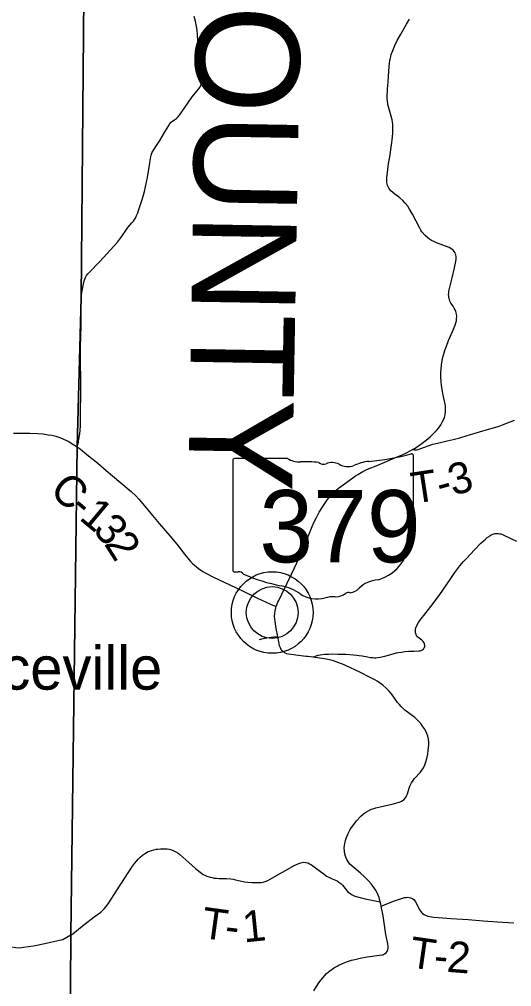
# Model space of a CAD drawing. Extents: x 0 to 34, y 0 to 22.
# Drawn here: x 7.038 to 7.936, y 15.399 to 17.164 of the extents above; entities that cross this region are included whole.
import ezdxf

# ---------------------------------------------------------------- set-up
doc = ezdxf.new("R2010")
doc.units = 0
for name, color, linetype in [('GM_X_Corporation', 7, 'Continuous'), ('GM_X_County_Road', 7, 'Continuous'), ('GM_X_County_Road_Text', 7, 'Continuous'), ('GM_X_County_Text', 7, 'Continuous'), ('GM_X_State_Location', 7, 'Continuous'), ('GM_X_State_Route', 7, 'Continuous'), ('GM_X_State_Shield', 7, 'Continuous'), ('GM_X_Township_Road', 7, 'Continuous'), ('GM_X_Township_Road_Text', 7, 'Continuous'), ('GM_X_Township_Text', 7, 'Continuous'), ('GM_X_Unincorporated', 7, 'Continuous'), ('GM_X_Unincorporated_Location', 7, 'Continuous'), ('GM_X_Unincorporated_Text', 7, 'Continuous')]:
    doc.layers.add(name, color=color, linetype=linetype)

msp = doc.modelspace()

# ---------------------------------------------------------------- linework, layer by layer
at = {"layer": 'GM_X_Corporation'}
msp.add_lwpolyline([(7.1227, 14.1), (8.9, 14.1), (8.9, 20.9), (7.231, 20.9), (7.2244, 20.2649), (7.1982, 19.2496), (7.1981, 19.2461), (7.1974, 19.2018), (7.1957, 19.0991), (7.1992, 18.9556), (7.197, 18.9465), (7.1949, 18.8464), (7.1846, 18.5133), (7.1817, 18.3306), (7.1804, 18.2238), (7.1572, 17.4131), (7.1504, 16.6562), (7.1434, 16.3848), (7.1318, 15.4937)], close=True, dxfattribs=at)
at = {"layer": 'GM_X_County_Road'}
for points in [[(7.0275, 16.409), (7.0571, 16.4092), (7.0714, 16.4087), (7.0815, 16.4078), (7.0903, 16.4063), (7.0974, 16.4054), (7.1045, 16.4037), (7.1116, 16.4013), (7.1184, 16.3986), (7.127, 16.3944), (7.1356, 16.3895), (7.1436, 16.3842)], [(7.1436, 16.3842), (7.1497, 16.3798), (7.161, 16.3705), (7.1808, 16.3543), (7.196, 16.3409), (7.2232, 16.3184), (7.2418, 16.3028), (7.2505, 16.2949), (7.2559, 16.2891), (7.2603, 16.284), (7.281, 16.2592), (7.293, 16.2445), (7.3126, 16.2219), (7.3252, 16.2067), (7.3296, 16.2011), (7.3373, 16.191)], [(7.3373, 16.191), (7.3387, 16.1891), (7.345, 16.1812), (7.3503, 16.175), (7.3537, 16.1714), (7.3607, 16.1653), (7.3645, 16.1623), (7.3691, 16.1592), (7.3728, 16.1569), (7.377, 16.1545), (7.3922, 16.1465), (7.4215, 16.1325), (7.4459, 16.1209), (7.4719, 16.1082), (7.4957, 16.0973), (7.5062, 16.093)]]:
    msp.add_lwpolyline(points, dxfattribs=at)
at = {"layer": 'GM_X_State_Route'}
msp.add_line((7.5737, 16.0006), (7.5639, 16.0017), dxfattribs=at)
for points in [[(7.755, 16.3792), (7.7595, 16.3818), (7.7641, 16.3849), (7.7698, 16.3891), (7.7825, 16.399), (7.7874, 16.4033), (7.7958, 16.411), (7.7985, 16.4139), (7.8026, 16.4189), (7.8041, 16.4209), (7.8067, 16.4247), (7.809, 16.4291), (7.8111, 16.4334), (7.8129, 16.4378), (7.8142, 16.4429), (7.8148, 16.448), (7.8151, 16.4526), (7.8148, 16.4587), (7.8143, 16.4627), (7.8134, 16.4677), (7.8104, 16.4814), (7.8088, 16.4893), (7.8077, 16.4965), (7.8069, 16.5033), (7.8066, 16.5113), (7.8067, 16.5204), (7.807, 16.5263), (7.8078, 16.5338), (7.809, 16.5418), (7.8103, 16.548), (7.812, 16.5543), (7.8143, 16.5619), (7.8165, 16.5681), (7.8207, 16.5785), (7.8278, 16.595), (7.8327, 16.6066), (7.834, 16.6107), (7.8348, 16.6141), (7.8353, 16.6177), (7.8356, 16.6228), (7.8351, 16.6265), (7.8346, 16.6288), (7.8336, 16.6315), (7.8324, 16.6343), (7.8309, 16.6371), (7.8287, 16.6409), (7.825, 16.6464), (7.823, 16.6504), (7.822, 16.6535), (7.8213, 16.6563), (7.8208, 16.6591), (7.8207, 16.6621), (7.8208, 16.665), (7.8212, 16.6681), (7.8226, 16.6756), (7.8269, 16.693), (7.8313, 16.7111), (7.834, 16.7227), (7.8347, 16.7267), (7.8345, 16.7311), (7.8338, 16.7346), (7.8333, 16.7361), (7.8324, 16.7383), (7.831, 16.7409), (7.8287, 16.7435), (7.8248, 16.7464), (7.8216, 16.7481), (7.7983, 16.7567), (7.7936, 16.7588), (7.7896, 16.7609), (7.7859, 16.7633), (7.7827, 16.7656), (7.7776, 16.77), (7.7721, 16.7769), (7.77, 16.7799), (7.7679, 16.7833), (7.7548, 16.8089), (7.7496, 16.8182), (7.746, 16.8234), (7.7415, 16.8289), (7.7371, 16.8336), (7.7318, 16.8384), (7.7229, 16.8454), (7.7155, 16.8515), (7.7134, 16.8541), (7.7119, 16.8563), (7.7106, 16.8588), (7.7095, 16.8614), (7.7086, 16.8641), (7.7081, 16.8668), (7.7078, 16.8696), (7.708, 16.8752), (7.7098, 16.8905), (7.7112, 16.9013), (7.7132, 16.9136), (7.7173, 16.9395), (7.718, 16.9445), (7.7189, 16.9558), (7.7191, 16.9629), (7.7188, 16.9729), (7.7182, 16.9775), (7.7176, 16.981), (7.7161, 16.988), (7.7111, 17.005), (7.7101, 17.0088), (7.7096, 17.0115), (7.709, 17.0147), (7.7085, 17.0209), (7.7094, 17.0377), (7.7102, 17.0495), (7.7115, 17.0696), (7.7129, 17.0851), (7.7134, 17.0884), (7.714, 17.0916), (7.7152, 17.0967), (7.7162, 17.1004), (7.7187, 17.1078), (7.7224, 17.1168), (7.7266, 17.1255), (7.7333, 17.1375), (7.7436, 17.1553), (7.7493, 17.165)], [(7.6913, 16.3511), (7.7271, 16.3661), (7.7347, 16.3693), (7.7437, 16.3734), (7.7505, 16.3768), (7.755, 16.3792)], [(7.5062, 16.093), (7.5095, 16.1007), (7.511, 16.1039), (7.5164, 16.1153), (7.5347, 16.1532), (7.5486, 16.1828), (7.5521, 16.1907), (7.5576, 16.2038), (7.5705, 16.2358), (7.5718, 16.2389), (7.575, 16.246), (7.5789, 16.254), (7.5849, 16.2649), (7.5914, 16.2754), (7.596, 16.2826), (7.5999, 16.2883), (7.6021, 16.2912), (7.6053, 16.295), (7.6115, 16.3018), (7.6156, 16.3054), (7.6196, 16.3087), (7.637, 16.3213), (7.6509, 16.3313), (7.6553, 16.3341), (7.6641, 16.3392), (7.6729, 16.3433), (7.6913, 16.3511)], [(7.5639, 16.0017), (7.561, 16.002), (7.5422, 16.0041), (7.5287, 16.0062), (7.5258, 16.0069), (7.5229, 16.008), (7.5212, 16.0091), (7.518, 16.0115), (7.5155, 16.0147), (7.5141, 16.0173), (7.5126, 16.0215), (7.5111, 16.0284), (7.5092, 16.0384), (7.5065, 16.0531), (7.5045, 16.0656), (7.5038, 16.0705), (7.5035, 16.0756), (7.5037, 16.0804), (7.5043, 16.0852), (7.5055, 16.0904), (7.5062, 16.093)], [(7.5751, 15.392), (7.5828, 15.4043), (7.5858, 15.4086), (7.5911, 15.4153), (7.5983, 15.4232), (7.604, 15.428), (7.6083, 15.4312), (7.6126, 15.4341), (7.6174, 15.4369), (7.6213, 15.439), (7.6248, 15.4406), (7.6315, 15.4433), (7.6382, 15.4457), (7.6435, 15.4474), (7.6496, 15.4491), (7.6592, 15.4513), (7.6724, 15.4535), (7.6987, 15.4571), (7.7, 15.4574), (7.7022, 15.4582), (7.7037, 15.4591), (7.7065, 15.4612), (7.7084, 15.4636), (7.7097, 15.4669), (7.7103, 15.4696), (7.7104, 15.4727), (7.7096, 15.4773), (7.7061, 15.4947), (7.7036, 15.5114), (7.7014, 15.5285), (7.6978, 15.5463), (7.697, 15.5499), (7.6961, 15.5539), (7.694, 15.5619), (7.6922, 15.5663), (7.6903, 15.5704), (7.6883, 15.5741), (7.686, 15.578), (7.6833, 15.5821), (7.6797, 15.5868), (7.6747, 15.5925), (7.6674, 15.5995), (7.6599, 15.6064), (7.6408, 15.623), (7.6368, 15.6281), (7.6348, 15.6315), (7.6331, 15.6355), (7.6324, 15.6376), (7.6315, 15.641), (7.6307, 15.6463), (7.6305, 15.6519), (7.6309, 15.6573), (7.6313, 15.6597), (7.6318, 15.6627), (7.6334, 15.6687), (7.6354, 15.6744), (7.6375, 15.679), (7.6405, 15.6846), (7.6438, 15.69), (7.6477, 15.6955), (7.6526, 15.7016), (7.6604, 15.7106), (7.6655, 15.7149), (7.6708, 15.7185), (7.6754, 15.721), (7.6803, 15.7231), (7.6841, 15.7244), (7.688, 15.7255), (7.6982, 15.728), (7.7176, 15.7324), (7.7307, 15.7361), (7.7323, 15.7366), (7.7346, 15.7378), (7.7394, 15.741), (7.743, 15.7456), (7.7446, 15.7487), (7.7455, 15.751), (7.7485, 15.7616), (7.7499, 15.7653), (7.751, 15.7677), (7.7531, 15.7713), (7.7558, 15.7756), (7.7579, 15.7783), (7.7608, 15.7817), (7.767, 15.7882), (7.7693, 15.7909), (7.772, 15.7942), (7.7747, 15.7986), (7.7774, 15.804), (7.7793, 15.8094), (7.781, 15.8156), (7.7826, 15.8238), (7.7835, 15.8306), (7.7845, 15.8401), (7.7843, 15.8457), (7.7838, 15.851), (7.7827, 15.8561), (7.7812, 15.861), (7.7795, 15.8644), (7.7764, 15.87), (7.7733, 15.8746), (7.7697, 15.8793), (7.764, 15.8858), (7.7588, 15.8903), (7.7411, 15.9041), (7.7386, 15.9063), (7.7343, 15.9103), (7.7302, 15.9149), (7.7277, 15.918), (7.7163, 15.9336), (7.7122, 15.9384), (7.7074, 15.9434), (7.7008, 15.9493), (7.6964, 15.9527), (7.6902, 15.9569), (7.686, 15.9594), (7.6777, 15.9637), (7.659, 15.973), (7.6324, 15.9854), (7.6261, 15.9882), (7.6218, 15.9899), (7.6174, 15.9915), (7.6109, 15.9936), (7.6032, 15.9956), (7.5946, 15.9974), (7.5855, 15.9989), (7.5737, 16.0006)]]:
    msp.add_lwpolyline(points, dxfattribs=at)
at = {"layer": 'GM_X_State_Shield'}
for p, q in [((7.5269, 16.3631), (7.4303, 16.3631)), ((7.7567, 16.2634), (7.7567, 16.3681)), ((7.4271, 16.3596), (7.4271, 16.1595)), ((7.7566, 16.2634), (7.7567, 16.2634))]:
    msp.add_line(p, q, dxfattribs=at)
for centre, major_axis, start_param, end_param in [((7.4309, 16.3601), (0.00382, 0), 1.712693, 3.28349), ((7.5498, 16.3863), (0.037, 0), 4.042523, 4.731795), ((7.6393, 16.6359), (0.3495, 0), 4.814394, 5.042369), ((7.753, 16.3685), (0.00367, 0), 6.141152, 7.989035), ((7.5621, 16.2507), (0.133, 0), 1.404758, 1.657858), ((7.5923, 16.3611), (0.0107, 0), 3.836095, 5.185415), ((7.608, 16.338), (0.0222, 0), 0.950623, 2.079405), ((7.6367, 16.3697), (0.0267, 0), 4.081561, 5.145723), ((7.6839, 16.302), (0.0703, 0), 1.699011, 2.107814), ((7.7558, 16.2557), (0.00568, 0), 1.883978, 3.671073), ((7.7528, 16.263), (0.00393, 0), 5.05454, 6.418171), ((7.7197, 16.2424), (0.0341, 0), 5.934695, 6.695948), ((7.7698, 16.2196), (0.0248, 0), 2.387724, 3.262537), ((7.6588, 16.2062), (0.0874, 0), 5.101752, 6.440018), ((7.4309, 16.1591), (0.00385, 0), 3.00124, 4.508301), ((7.4315, 16.1796), (0.0294, 0), 4.665946, 4.897461), ((7.4375, 16.148), (0.0106, 0), 0.519207, 1.627899), ((7.5713, 16.3278), (0.2524, 0), 4.195997, 4.488961), ((7.6957, 16.1033), (0.0479, 0), 1.647645, 2.488434), ((7.4961, 16.0696), (0.079, 0), 0.823519, 1.323587), ((7.5815, 16.147), (0.0501, 0), 4.026481, 4.996735), ((7.6141, 16.132), (0.0267, 0), 4.691044, 5.507374), ((7.6383, 16.1126), (0.00752, 0), 1.147584, 2.315152), ((7.635, 16.1401), (0.0282, 0), 4.937069, 5.64225), ((7.6104, 16.0778), (0.0412, 0), 1.495662, 1.94098)]:
    msp.add_ellipse(centre, major_axis=major_axis, ratio=0.8, start_param=start_param, end_param=end_param, dxfattribs=at)
at = {"layer": 'GM_X_Township_Road'}
for points in [[(7.1436, 16.3842), (7.1457, 16.3928), (7.146, 16.3953), (7.1483, 16.408), (7.149, 16.4145), (7.1493, 16.4228), (7.1496, 16.4544), (7.1501, 16.4756), (7.1499, 16.5048), (7.1495, 16.5414), (7.1497, 16.5644), (7.1503, 16.5874), (7.1507, 16.6041), (7.1506, 16.63), (7.1504, 16.6526), (7.1506, 16.6557), (7.1511, 16.6613), (7.1519, 16.6659), (7.1525, 16.6687), (7.1563, 16.687), (7.1573, 16.6903), (7.1585, 16.6931), (7.1605, 16.6967), (7.1628, 16.6999), (7.1652, 16.7025), (7.1849, 16.7224), (7.217, 16.7579), (7.2188, 16.7601), (7.2226, 16.7652), (7.2255, 16.7695), (7.2319, 16.7793), (7.2332, 16.781), (7.2359, 16.7844), (7.2433, 16.7928), (7.246, 16.796), (7.248, 16.7991), (7.2495, 16.8018), (7.2516, 16.8063), (7.2538, 16.8116), (7.2552, 16.8156), (7.2627, 16.8374), (7.2661, 16.8502), (7.2714, 16.8758), (7.2746, 16.8944), (7.278, 16.9141), (7.2785, 16.9164), (7.2791, 16.9186), (7.2803, 16.9218), (7.2819, 16.9246), (7.287, 16.9321), (7.2943, 16.9431), (7.3029, 16.9577), (7.3093, 16.9687), (7.3118, 16.9731), (7.3145, 16.9767), (7.3179, 16.9792), (7.3224, 16.9821), (7.3244, 16.9835), (7.3263, 16.9853), (7.3297, 16.9893), (7.3452, 17.0117), (7.353, 17.0227), (7.3644, 17.0369), (7.3668, 17.0403), (7.3685, 17.0432), (7.3695, 17.0452), (7.3711, 17.0498), (7.3721, 17.0544), (7.3725, 17.0582), (7.3724, 17.0619), (7.3718, 17.0659), (7.3708, 17.0699), (7.3677, 17.079), (7.3664, 17.0838), (7.3654, 17.0897), (7.365, 17.0934), (7.3647, 17.097), (7.3641, 17.1061), (7.3636, 17.1253), (7.3628, 17.1364), (7.3619, 17.1449), (7.361, 17.1512), (7.3591, 17.161), (7.3568, 17.1698)], [(7.755, 16.3792), (7.7583, 16.3787), (7.7601, 16.3786), (7.7622, 16.3788), (7.7652, 16.3797), (7.7683, 16.3806), (7.792, 16.389), (7.8058, 16.3925), (7.818, 16.3952), (7.829, 16.3977), (7.8413, 16.4008), (7.8528, 16.4042), (7.8605, 16.4068), (7.869, 16.4094), (7.8768, 16.4117), (7.8933, 16.4165), (7.9026, 16.419), (7.9126, 16.4221), (7.9188, 16.4245), (7.9329, 16.4302), (7.9408, 16.4333)], [(7.5737, 16.0006), (7.5792, 16.0028), (7.5831, 16.0041), (7.5867, 16.0049), (7.5942, 16.0058), (7.602, 16.0063), (7.6087, 16.0064), (7.6184, 16.0063), (7.6332, 16.0059), (7.6472, 16.0047), (7.663, 16.003), (7.6729, 16.0013), (7.6785, 16.0002), (7.6818, 15.9997), (7.6848, 15.9995), (7.6878, 15.9996), (7.6911, 15.9999), (7.6959, 16.0007), (7.7044, 16.0026), (7.7198, 16.0068), (7.7254, 16.0083), (7.7293, 16.0092), (7.7345, 16.0099), (7.7408, 16.0106), (7.7482, 16.0112), (7.7572, 16.0115), (7.7665, 16.012), (7.7687, 16.0122), (7.7706, 16.0127), (7.7728, 16.014), (7.7747, 16.0154), (7.7763, 16.0176), (7.777, 16.0195), (7.7773, 16.0218), (7.7767, 16.025), (7.7758, 16.0269), (7.7744, 16.029), (7.7717, 16.0315), (7.7668, 16.0353), (7.764, 16.0377), (7.7624, 16.04), (7.7615, 16.0417), (7.7605, 16.0447), (7.7602, 16.0459), (7.76, 16.0481), (7.7603, 16.0512), (7.7611, 16.0542), (7.7628, 16.0581), (7.7659, 16.0638), (7.7685, 16.0679), (7.7723, 16.0731), (7.7752, 16.0767), (7.7925, 16.0987), (7.8044, 16.1148), (7.817, 16.1326), (7.8258, 16.1459), (7.8321, 16.1549), (7.8411, 16.1673), (7.8477, 16.1749), (7.853, 16.1806), (7.8676, 16.1963), (7.8797, 16.2088), (7.8877, 16.216), (7.891, 16.2186), (7.8943, 16.2208), (7.8964, 16.2224), (7.8985, 16.2236), (7.9013, 16.2249), (7.9038, 16.2256), (7.9055, 16.226), (7.9089, 16.2263), (7.9112, 16.2262), (7.9139, 16.2258), (7.9161, 16.2253), (7.9188, 16.2243), (7.9354, 16.2163), (7.9447, 16.2125)], [(7.476, 16.0328), (7.4852, 16.0351), (7.4937, 16.0365), (7.5019, 16.0375), (7.5092, 16.0384)], [(7.132, 15.4932), (7.1356, 15.496), (7.1458, 15.5045), (7.1556, 15.5119), (7.1747, 15.5267), (7.1865, 15.5354), (7.189, 15.5377), (7.193, 15.542), (7.1978, 15.5479), (7.2009, 15.5523), (7.2154, 15.574), (7.2365, 15.6068), (7.2411, 15.6144), (7.2445, 15.6191), (7.2482, 15.624), (7.2516, 15.6282), (7.2554, 15.6324), (7.2581, 15.6353), (7.2627, 15.6393), (7.2677, 15.6427), (7.273, 15.6457), (7.2757, 15.6468), (7.2787, 15.6479), (7.2831, 15.649), (7.2873, 15.6499), (7.2907, 15.6504), (7.2953, 15.6509), (7.2998, 15.6511), (7.3075, 15.6508), (7.3109, 15.6502), (7.3153, 15.649), (7.3195, 15.6474), (7.3236, 15.6454), (7.3274, 15.6429), (7.3306, 15.6403), (7.3471, 15.6259), (7.3589, 15.6152), (7.3674, 15.6083), (7.37, 15.6063), (7.3734, 15.6041), (7.3761, 15.6027), (7.3797, 15.601), (7.3856, 15.5991), (7.3894, 15.5982), (7.3934, 15.5975), (7.3974, 15.597), (7.4014, 15.5968), (7.4154, 15.5967), (7.4233, 15.596), (7.428, 15.5954), (7.4322, 15.5945), (7.4463, 15.5911), (7.4488, 15.5906), (7.4544, 15.5898), (7.4625, 15.5892), (7.4788, 15.5894), (7.4827, 15.59), (7.4862, 15.591), (7.4913, 15.5932), (7.4952, 15.5952), (7.511, 15.6044), (7.5189, 15.6089), (7.5388, 15.6201), (7.5477, 15.6242), (7.5514, 15.6255), (7.5534, 15.626), (7.5563, 15.6263), (7.5603, 15.6261), (7.5639, 15.6254), (7.5673, 15.6236), (7.5705, 15.6216), (7.5779, 15.6163), (7.5935, 15.6044), (7.5983, 15.601), (7.6032, 15.5984), (7.6081, 15.5963), (7.6173, 15.5922), (7.6205, 15.5902), (7.624, 15.5873), (7.627, 15.5843), (7.6344, 15.5753), (7.6365, 15.573), (7.6409, 15.5693), (7.6447, 15.5669), (7.6486, 15.565), (7.6516, 15.5639), (7.6547, 15.563), (7.6685, 15.5598), (7.6961, 15.5539)], [(7.6978, 15.5463), (7.7203, 15.5552), (7.7327, 15.5597), (7.7381, 15.5614), (7.7403, 15.5619), (7.7425, 15.5622), (7.7454, 15.5624), (7.7489, 15.5621), (7.7509, 15.5615), (7.753, 15.5607), (7.7552, 15.5595), (7.7578, 15.5576), (7.7592, 15.5559), (7.7602, 15.5543), (7.7684, 15.5386), (7.7698, 15.5365), (7.7714, 15.5344), (7.7733, 15.5329), (7.7759, 15.5309), (7.7784, 15.5298), (7.783, 15.5281), (7.7862, 15.5273), (7.7892, 15.5267), (7.7935, 15.5261), (7.8255, 15.5238), (7.8562, 15.5217), (7.8835, 15.5197), (7.9098, 15.5179), (7.9395, 15.5159)], [(7.132, 15.4932), (7.1171, 15.485), (7.1113, 15.4834), (7.0946, 15.4798), (7.0842, 15.4777), (7.0636, 15.4731), (7.0456, 15.4705), (7.0382, 15.4698), (7.0317, 15.47), (7.0227, 15.4712), (7.0075, 15.4727), (6.9954, 15.4736), (6.9872, 15.4749), (6.9806, 15.4764), (6.9745, 15.4797), (6.9683, 15.4824)]]:
    msp.add_lwpolyline(points, dxfattribs=at)
at = {"layer": 'GM_X_Township_Text'}
msp.add_lwpolyline([(7.1227, 14.1), (7.1318, 15.4937), (7.1434, 16.3848), (7.1504, 16.6562), (7.1572, 17.4131), (7.1804, 18.2238), (7.1817, 18.3306), (7.1846, 18.5133), (7.1949, 18.8464), (7.197, 18.9465), (7.1992, 18.9556), (7.1957, 19.0991), (7.1536, 19.0995)], dxfattribs=at)
at = {"layer": 'GM_X_Unincorporated'}
for radius in [0.0744, 0.0472]:
    msp.add_circle((7.499, 16.082), radius, dxfattribs=at)
at = {"layer": 'GM_X_Unincorporated_Location'}
msp.add_line((7.499, 16.082), (7.499, 16.082), dxfattribs=at)

# ---------------------------------------------------------------- texts
at = {"layer": 'GM_X_County_Road_Text'}
for s, rotation, p in [('C', 317.4404, (7.0908, 16.3015)), ('-', 319.682, (7.127, 16.2684)), ('1', 320.1295, (7.1452, 16.253)), ('3', 310.2976, (7.1702, 16.2323)), ('2', 302.4516, (7.1916, 16.2073))]:
    msp.add_text(s, height=0.0568, rotation=rotation, dxfattribs=at).set_placement(p)
at = {"layer": 'GM_X_County_Text'}
msp.add_text('BELMONT COUNTY', height=0.189394, rotation=269.0214, dxfattribs=at).set_placement((7.3864, 18.6686))
at = {"layer": 'GM_X_State_Location'}
for s in ['s', 'r']:
    msp.add_text(s, height=0.000189, dxfattribs=at).set_placement((7.5882, 16.2463))
msp.add_text('379', height=0.000189, rotation=0, dxfattribs=at).set_placement((7.5213, 16.2325))
at = {"layer": 'GM_X_State_Shield'}
msp.add_text('379', height=0.13184, dxfattribs=at).set_placement((7.4756, 16.1736))
at = {"layer": 'GM_X_Township_Road_Text'}
for s, rotation, p in [('3', 15.3035, (7.8287, 16.2948)), ('T', 8.7204, (7.7569, 16.2804)), ('-', 15.7151, (7.8063, 16.2885)), ('T', 352.1563, (7.3677, 15.4887)), ('1', 5.7931, (7.4476, 15.4799)), ('-', 353.2577, (7.4109, 15.4828)), ('T', 351.8581, (7.7469, 15.4349)), ('2', 355.4675, (7.8161, 15.4265)), ('-', 355.1814, (7.7925, 15.4285))]:
    msp.add_text(s, height=0.0568, rotation=rotation, dxfattribs=at).set_placement(p)
at = {"layer": 'GM_X_Unincorporated_Text'}
msp.add_text('Temperanceville', height=0.078977, rotation=0, dxfattribs=at).set_placement((6.5238, 15.9413))

doc.saveas('drawing.dxf')
